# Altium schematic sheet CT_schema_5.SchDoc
size 369 x 243 mm
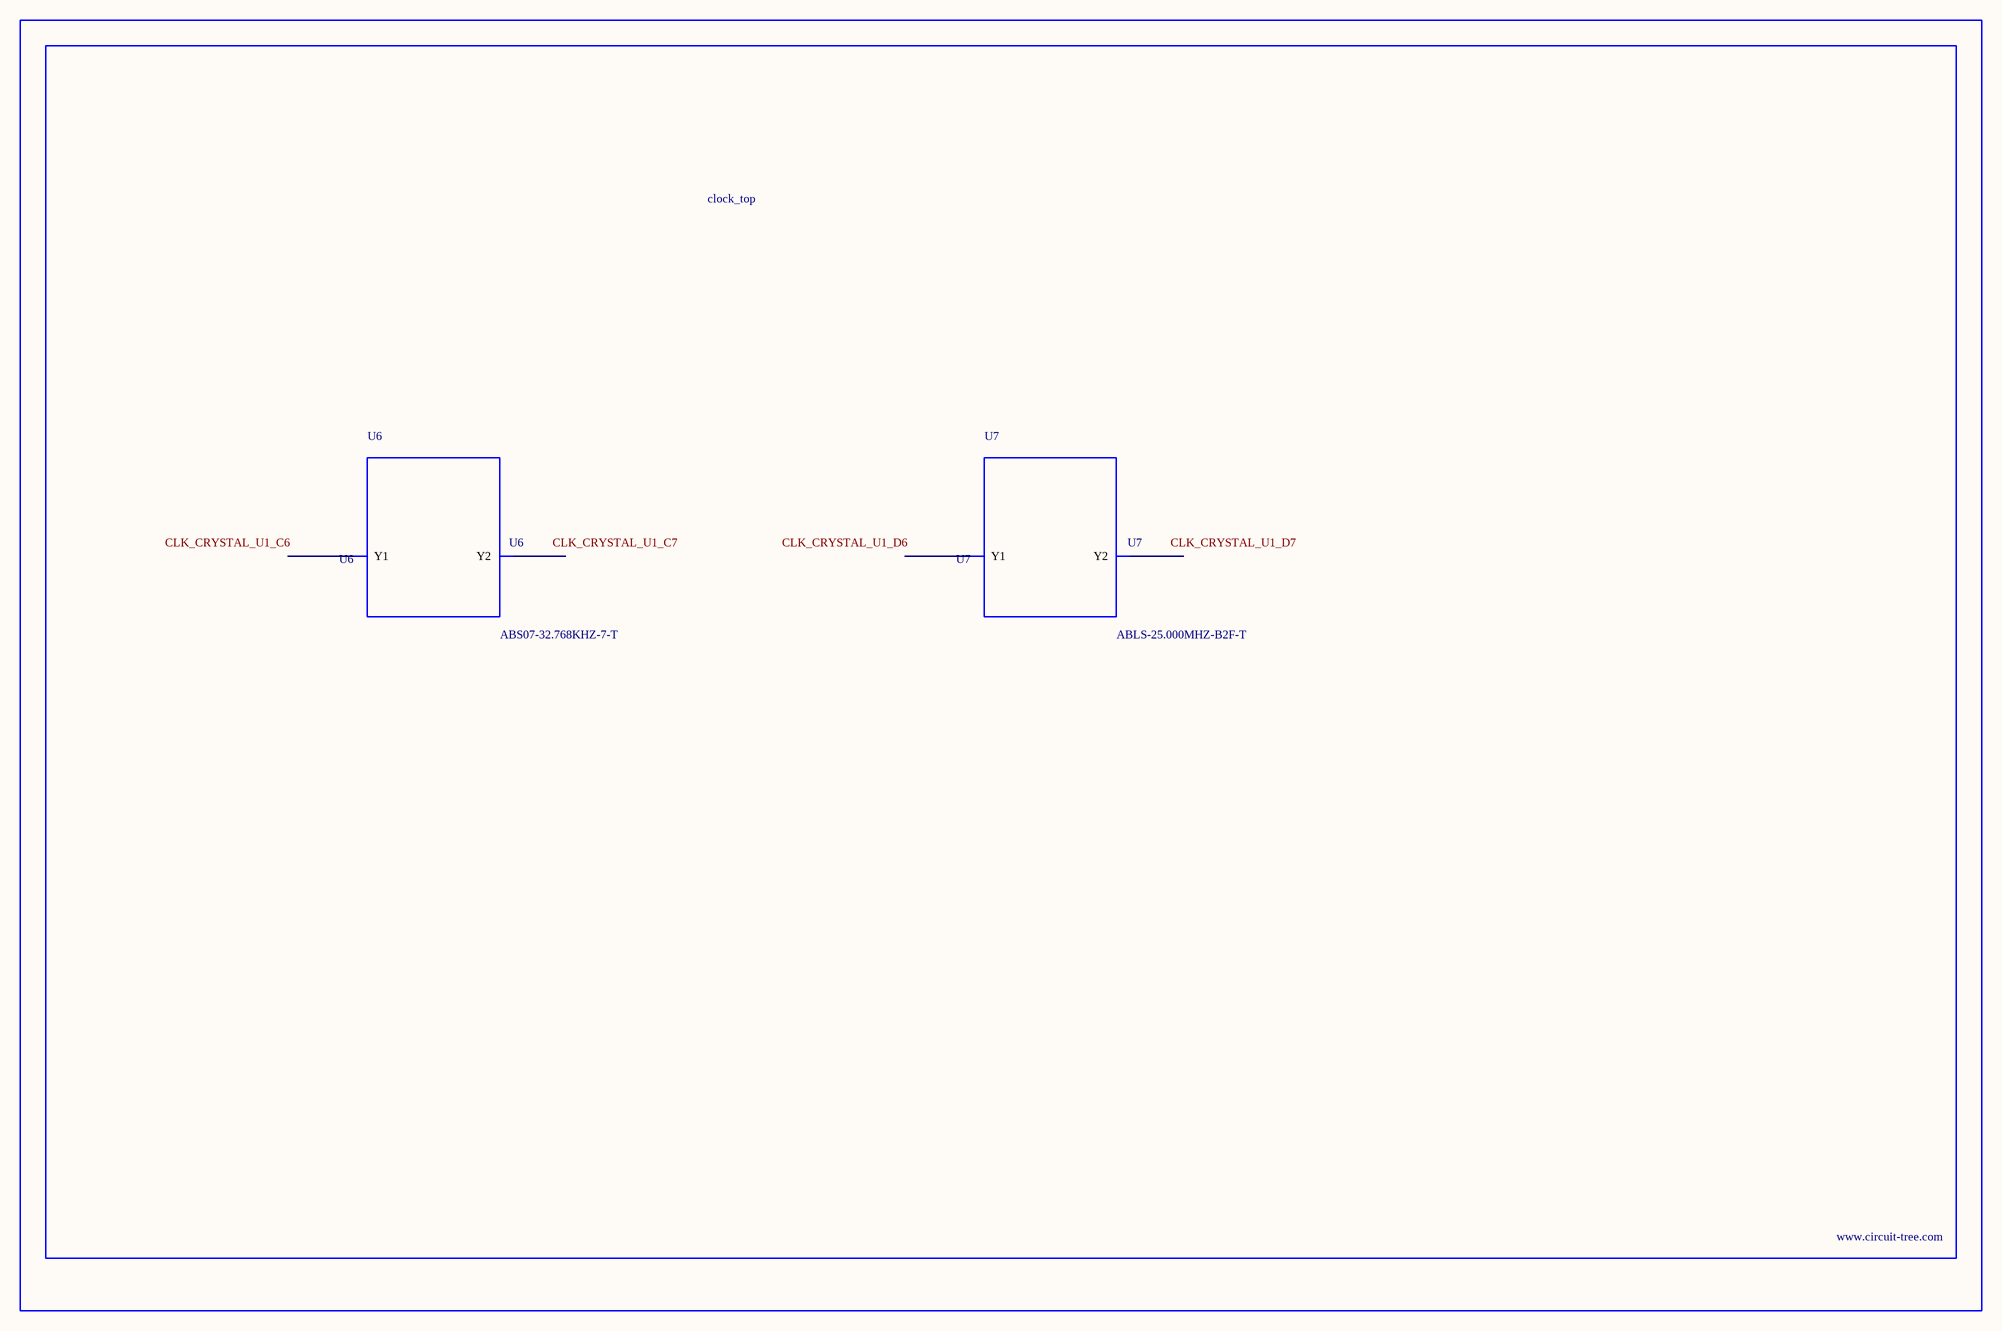
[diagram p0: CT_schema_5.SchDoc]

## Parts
BORDER4  (no value)
U6  ABS07-32.768KHZ-7-T  [ABS07-32.768KHZ-7-T]
U7  ABLS-25.000MHZ-B2F-T  [ABLS-25.000MHZ-B2F-T]

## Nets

Not connected (* = marked no-connect by the designer): U6 1(Y1) 2(Y2); U7 1(Y1) 2(Y2)

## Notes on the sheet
- Labels drawn without touching a wire or pin: CLK_CRYSTAL_U1_C6, CLK_CRYSTAL_U1_C7, CLK_CRYSTAL_U1_D6, CLK_CRYSTAL_U1_D7

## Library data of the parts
BORDER4 = BORDER_PAGE4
